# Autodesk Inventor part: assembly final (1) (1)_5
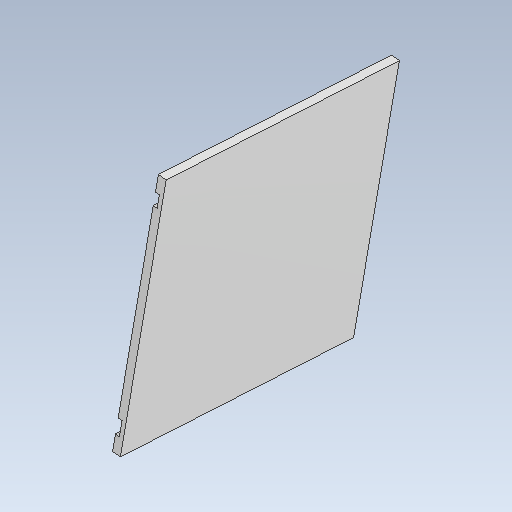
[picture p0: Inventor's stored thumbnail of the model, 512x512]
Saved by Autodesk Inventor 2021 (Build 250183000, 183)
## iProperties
Created: 2021-07
Part Number: assembly final (1) (1)_5
Material: Generic
Document SubType Name: Modeling
Designer: TARUN
Density: 1 g/cm^3
Appearance: Default
Author: TARUN
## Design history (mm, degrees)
feature "Base1"
body "Solid1"
